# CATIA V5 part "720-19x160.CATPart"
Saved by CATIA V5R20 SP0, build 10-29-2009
Part number: 720-19x160
Definition: NONE
Nomenclature: 720-19x160
Source: Unknown
Description: 720-19x160
Bounding box of the stored display mesh (mm): x 0 to 160, y -9.5 to 9.5, z -9.5 to 9.5
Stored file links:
  C:\Users\Utente\Desktop\IO LAVORO\3D X SITO CF\X SITO\720\720-19x160.CATPart
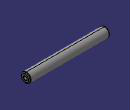
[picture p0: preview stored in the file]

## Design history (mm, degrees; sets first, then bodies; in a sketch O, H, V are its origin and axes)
Body1 "720-19x160" (main body)
  Solid1: solid without history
